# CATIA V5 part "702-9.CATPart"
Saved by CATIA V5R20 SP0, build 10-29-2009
Part number: 702-9
Source: Unknown
Property "ARTICLENO": "702-9"
Property "BOMINFO": "702-9"
Property "CODE": "702-9"
Property "L": "350.000"
Property "LINA": "702-9"
Property "NB": "702-9"
Property "NBSYN": "$CODE."
Property "NN": "702"
Property "SUPPLIER": "CF"
Bounding box of the stored display mesh (mm): x -107 to 0, y 0 to 350, z -15 to 15
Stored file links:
  C:\Users\Utente\Desktop\3D files 702\702-9.CATPart
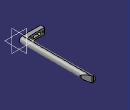
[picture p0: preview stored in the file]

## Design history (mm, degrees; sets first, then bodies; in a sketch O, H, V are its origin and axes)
Body1 "Geometry.1" (main body)
  Solid1 "702-9.catpart": solid without history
